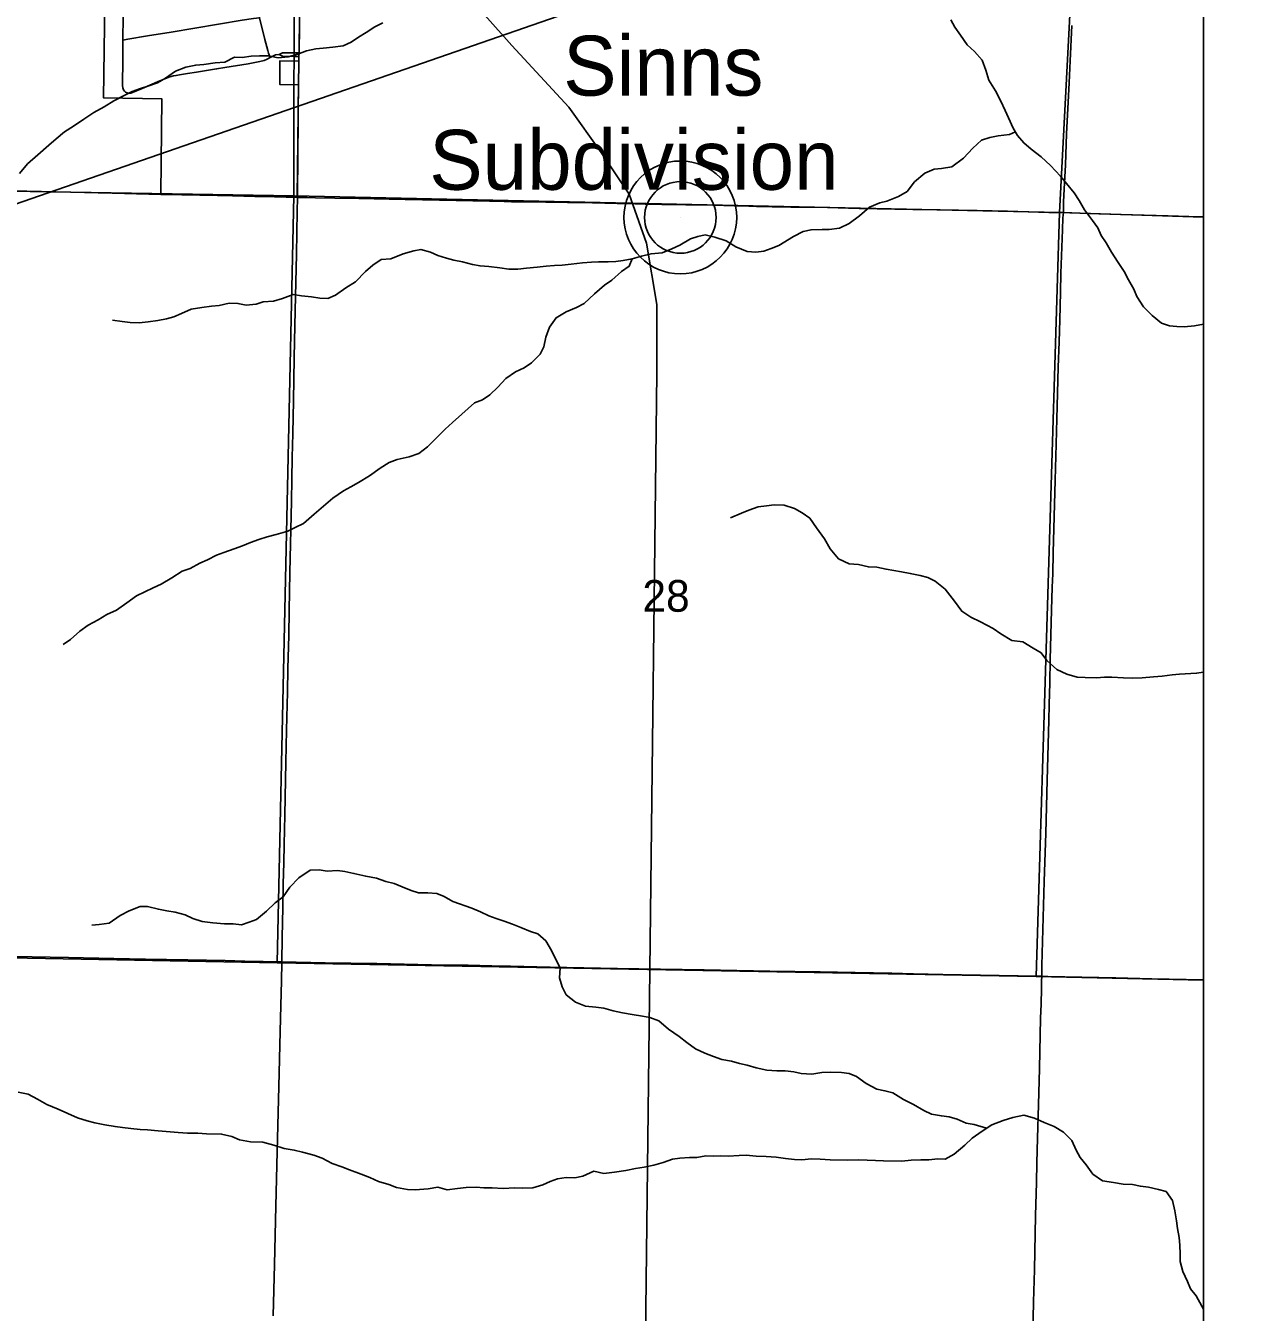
# Model space of a CAD drawing. Extents: x 0 to 34, y 0 to 22.
# Drawn here: x 7.346 to 8.95, y 15.064 to 16.761 of the extents above; entities that cross this region are included whole.
import ezdxf

# ---------------------------------------------------------------- set-up
doc = ezdxf.new("R2010")
doc.units = 0
for name, color, linetype in [('GM_X_City_Street', 7, 'Continuous'), ('GM_X_Corporation', 7, 'Continuous'), ('GM_X_County_Road', 7, 'Continuous'), ('GM_X_Minor_River', 7, 'Continuous'), ('GM_X_Rail_Line', 7, 'Continuous'), ('GM_X_Section_Text', 7, 'Continuous'), ('GM_X_Township_Road', 7, 'Continuous'), ('GM_X_Unincorporated', 7, 'Continuous'), ('GM_X_Unincorporated_Location', 7, 'Continuous'), ('GM_X_Unincorporated_Text', 7, 'Continuous'), ('GM_X_US_Route', 7, 'Continuous'), ('SH_Data', 7, 'Continuous')]:
    doc.layers.add(name, color=color, linetype=linetype)

msp = doc.modelspace()

# ---------------------------------------------------------------- linework, layer by layer
at = {"layer": 'GM_X_City_Street'}
for points in [[(7.6688, 16.7193), (7.6668, 16.7249), (7.6656, 16.7284), (7.6617, 16.743), (7.6546, 16.7718), (7.6511, 16.786), (7.6432, 16.8155), (7.6415, 16.8215), (7.6403, 16.8234), (7.639, 16.8245)], [(7.48, 16.6728), (7.4781, 16.6737), (7.4765, 16.6751), (7.4753, 16.6768), (7.4743, 16.6793), (7.4741, 16.6823), (7.4742, 16.6892), (7.4743, 16.7105), (7.4746, 16.7424), (7.4748, 16.774), (7.475, 16.7901), (7.4749, 16.7932)], [(7.4746, 16.7424), (7.4812, 16.7435), (7.507, 16.7478), (7.5383, 16.7529), (7.632, 16.7685), (7.6468, 16.7706), (7.6546, 16.7718)], [(7.48, 16.6728), (7.4822, 16.6723), (7.4849, 16.6722), (7.4874, 16.673), (7.4999, 16.6784), (7.5233, 16.6884), (7.5364, 16.6938), (7.5412, 16.695), (7.5447, 16.6957), (7.5493, 16.6965), (7.5596, 16.6981), (7.5717, 16.7002), (7.5981, 16.7043), (7.6091, 16.7063), (7.6397, 16.7112), (7.655, 16.714), (7.6611, 16.7156), (7.6647, 16.7171), (7.6681, 16.7189), (7.6688, 16.7193), (7.6724, 16.7212), (7.6758, 16.7227), (7.6806, 16.7234)], [(7.6806, 16.7234), (7.6849, 16.7257), (7.6861, 16.7257), (7.6996, 16.7255), (7.7069, 16.7253)], [(7.6806, 16.7234), (7.685, 16.7211), (7.6995, 16.7208), (7.7068, 16.7206)]]:
    msp.add_lwpolyline(points, dxfattribs=at)
at = {"layer": 'GM_X_Corporation'}
for points in [[(8.9, 14.4942), (8.9, 20.9), (2.1, 20.9)], [(8.9, 14.4942), (8.9, 20.5041)], [(7.4506, 16.7923), (7.4491, 16.6661), (7.5261, 16.6648), (7.5247, 16.5394), (7.7046, 16.5356), (7.7064, 16.6834), (7.6814, 16.6839), (7.6817, 16.7151), (7.7067, 16.7147), (7.7074, 16.7628)]]:
    msp.add_lwpolyline(points, dxfattribs=at)
for points in [[(6.7004, 17.5689), (7.7016, 17.5373), (7.6999, 16.5369), (6.6829, 16.5538)], [(7.7016, 17.5373), (8.7625, 17.5156), (8.7104, 16.5149), (7.6999, 16.5369)], [(8.9, 16.5086), (8.9, 17.5119), (8.7625, 17.5156), (8.7104, 16.5149)], [(6.6829, 16.5538), (7.6999, 16.5369), (7.6779, 15.5253), (6.6666, 15.5439)], [(7.6999, 16.5369), (8.7104, 16.5149), (8.6793, 15.5073), (7.6779, 15.5253)], [(8.9, 15.5025), (8.9, 16.5086), (8.7104, 16.5149), (8.6793, 15.5073)]]:
    msp.add_lwpolyline(points, close=True, dxfattribs=at)
at = {"layer": 'GM_X_County_Road'}
msp.add_line((7.7061, 16.6825), (7.7066, 16.7137), dxfattribs=at)
for points in [[(7.7075, 16.7611), (7.7075, 16.7621), (7.7078, 16.7914), (7.708, 16.8091), (7.7082, 16.8225), (7.7087, 16.8696), (7.7089, 16.8954), (7.7089, 16.9013)], [(7.7068, 16.7206), (7.7069, 16.7253), (7.7075, 16.7611)], [(8.7263, 16.7614), (8.7242, 16.715), (8.7229, 16.6858), (8.7217, 16.6604), (8.7194, 16.6188), (8.7179, 16.5779), (8.7162, 16.5456), (8.7156, 16.5289), (8.7153, 16.5148)], [(7.7066, 16.7137), (7.7067, 16.7162), (7.7068, 16.7206)], [(7.7047, 16.5348), (7.705, 16.5549), (7.7052, 16.5736), (7.7052, 16.5854), (7.7058, 16.6401), (7.7059, 16.6532), (7.7061, 16.6825)], [(7.6843, 15.5265), (7.6848, 15.5585), (7.6856, 15.5983), (7.6861, 15.6294), (7.6868, 15.6573), (7.6874, 15.6811), (7.6881, 15.7201), (7.6897, 15.7897), (7.6905, 15.832), (7.6917, 15.8823), (7.6923, 15.9134), (7.6933, 15.9569), (7.694, 15.9899), (7.695, 16.0402), (7.6969, 16.1341), (7.6975, 16.1633), (7.698, 16.1919), (7.6987, 16.2236), (7.6996, 16.2665), (7.7007, 16.3231), (7.7015, 16.366), (7.7024, 16.4039), (7.7035, 16.4598), (7.7046, 16.5164), (7.7047, 16.5348)], [(8.7153, 16.5148), (8.7479, 16.5138), (8.7907, 16.5124), (8.8535, 16.5106), (8.8945, 16.5092), (8.9, 16.509)], [(7.673, 15.0594), (7.6744, 15.1272), (7.6764, 15.2042), (7.6781, 15.2763), (7.6803, 15.3621), (7.682, 15.4348), (7.6828, 15.469), (7.6838, 15.5013), (7.6843, 15.5255), (7.6843, 15.5265)]]:
    msp.add_lwpolyline(points, dxfattribs=at)
at = {"layer": 'GM_X_Minor_River'}
for points in [[(8.6082, 16.7158), (8.5982, 16.7274), (8.5885, 16.7359), (8.5797, 16.749), (8.5723, 16.7594), (8.5668, 16.7689)], [(7.8174, 16.7653), (7.8071, 16.7598), (7.7955, 16.7524), (7.7856, 16.7462), (7.7756, 16.7395), (7.7652, 16.7348), (7.7515, 16.7328), (7.7386, 16.7315), (7.7291, 16.7306), (7.7169, 16.7281), (7.7055, 16.7238), (7.6925, 16.7203), (7.6792, 16.719), (7.6668, 16.7215), (7.6546, 16.7214), (7.6436, 16.7209), (7.6318, 16.7192), (7.622, 16.7198), (7.609, 16.7132), (7.5961, 16.7123), (7.5812, 16.7103), (7.5706, 16.7094), (7.5576, 16.7066), (7.5439, 16.7012), (7.5308, 16.6919), (7.5201, 16.6861), (7.5075, 16.6814), (7.4976, 16.6785), (7.4869, 16.6746), (7.4773, 16.6695), (7.4627, 16.6621), (7.4497, 16.6544), (7.4363, 16.6467), (7.4232, 16.6379), (7.4094, 16.6287), (7.3975, 16.6213), (7.3867, 16.612), (7.377, 16.6039), (7.3624, 16.5909), (7.3489, 16.579), (7.338, 16.5663)], [(8.9, 16.3676), (8.8881, 16.3654), (8.8745, 16.3642), (8.865, 16.3644), (8.8552, 16.3653), (8.8446, 16.3689), (8.8323, 16.3791), (8.8208, 16.3907), (8.8123, 16.4041), (8.8083, 16.4137), (8.8013, 16.4263), (8.7955, 16.4371), (8.7874, 16.449), (8.7789, 16.4628), (8.7716, 16.4751), (8.7653, 16.4847), (8.7606, 16.4946), (8.7536, 16.5043), (8.7432, 16.5185), (8.7362, 16.5308), (8.7296, 16.5408), (8.7196, 16.5531), (8.7115, 16.5628), (8.6985, 16.5767), (8.6862, 16.5883), (8.6727, 16.5984), (8.663, 16.6066), (8.6549, 16.6166), (8.649, 16.6262), (8.6428, 16.6396), (8.6384, 16.6495), (8.6326, 16.6618), (8.6257, 16.6756), (8.6168, 16.6894), (8.6129, 16.7028), (8.6082, 16.7158)], [(8.652, 16.6212), (8.6443, 16.6179), (8.6294, 16.616), (8.6184, 16.6139), (8.6073, 16.6103), (8.5958, 16.5999), (8.5834, 16.5865), (8.568, 16.575), (8.5547, 16.573), (8.5448, 16.5721), (8.5325, 16.5666), (8.5191, 16.5555), (8.5093, 16.5428), (8.4978, 16.5358), (8.4825, 16.53), (8.473, 16.5275), (8.4596, 16.5221), (8.4465, 16.5106), (8.4327, 16.5002), (8.42, 16.4944), (8.4063, 16.4924), (8.3969, 16.4926), (8.3825, 16.4921), (8.3718, 16.4897), (8.3591, 16.4831), (8.34, 16.4713), (8.3296, 16.4673), (8.3201, 16.4641), (8.3095, 16.4628), (8.2981, 16.4634), (8.2834, 16.4698), (8.2703, 16.4776), (8.2556, 16.4824), (8.2428, 16.4853), (8.2329, 16.4833), (8.2233, 16.48), (8.2091, 16.472), (8.1988, 16.4672), (8.1858, 16.4618), (8.1714, 16.4605), (8.1588, 16.4574), (8.1466, 16.4538), (8.1344, 16.4518), (8.1249, 16.4504), (8.1147, 16.4499), (8.1022, 16.4498), (8.0927, 16.4496), (8.0809, 16.4486), (8.0661, 16.4467), (8.0539, 16.4454), (8.044, 16.4452), (8.033, 16.4443), (8.0212, 16.4426), (8.0072, 16.4414), (7.9954, 16.4401), (7.9837, 16.4403), (7.9719, 16.442), (7.9572, 16.4435), (7.9458, 16.4444), (7.936, 16.4465), (7.9224, 16.4498), (7.9111, 16.4519), (7.9013, 16.4548), (7.89, 16.4584), (7.8802, 16.4624), (7.8677, 16.4661), (7.8582, 16.4644), (7.8441, 16.4605), (7.8281, 16.4539), (7.8151, 16.4527), (7.8044, 16.4453), (7.7948, 16.4371), (7.7816, 16.4234), (7.7685, 16.4156), (7.7551, 16.406), (7.7448, 16.4013), (7.7345, 16.4019), (7.7232, 16.4036), (7.7103, 16.405), (7.699, 16.4068), (7.6852, 16.4013), (7.6734, 16.3978), (7.6597, 16.3969), (7.6502, 16.394), (7.6373, 16.3928), (7.6263, 16.3949), (7.6146, 16.3951), (7.6016, 16.3923), (7.5914, 16.3914), (7.5788, 16.3894), (7.5647, 16.3874), (7.5517, 16.3819), (7.5418, 16.3772), (7.5323, 16.3747), (7.5205, 16.3723), (7.5079, 16.3706), (7.4961, 16.3694), (7.484, 16.37), (7.4738, 16.3713), (7.4609, 16.3731)], [(8.1465, 16.4538), (8.1426, 16.444), (8.1322, 16.437), (8.1195, 16.4255), (8.1099, 16.4192), (8.0968, 16.4077), (8.0833, 16.3947), (8.0729, 16.3896), (8.0595, 16.3838), (8.0461, 16.3761), (8.0375, 16.3637), (8.0327, 16.3506), (8.0298, 16.3377), (8.0251, 16.3279), (8.0135, 16.3164), (8.0039, 16.3098), (7.9924, 16.3047), (7.9797, 16.2958), (7.9693, 16.2846), (7.9585, 16.2746), (7.9488, 16.2676), (7.9385, 16.264), (7.9219, 16.2491), (7.9096, 16.238), (7.8999, 16.2291), (7.8868, 16.2164), (7.8764, 16.206), (7.8648, 16.1971), (7.8522, 16.1928), (7.8362, 16.189), (7.8259, 16.185), (7.814, 16.1777), (7.7998, 16.1677), (7.7852, 16.1589), (7.7752, 16.153), (7.7656, 16.1479), (7.7514, 16.1379), (7.7267, 16.1171), (7.7129, 16.1049), (7.7018, 16.0994), (7.6922, 16.0947), (7.6769, 16.09), (7.6651, 16.0869), (7.6541, 16.0837), (7.643, 16.0797), (7.6323, 16.0754), (7.6212, 16.0714), (7.6078, 16.0664), (7.5979, 16.0627), (7.586, 16.0569), (7.5761, 16.0522), (7.5631, 16.0452), (7.5527, 16.0416), (7.5393, 16.0332), (7.5251, 16.0247), (7.5144, 16.02), (7.5033, 16.0145), (7.4926, 16.0094), (7.4799, 16.0002), (7.466, 15.9902), (7.4534, 15.9848), (7.4419, 15.9778), (7.4289, 15.9708), (7.4177, 15.9627), (7.4054, 15.9516), (7.3958, 15.9453)], [(8.5019, 16.041), (8.4815, 16.0444), (8.4694, 16.0469), (8.458, 16.0475), (8.4452, 16.0504), (8.4327, 16.0514), (8.4188, 16.0582), (8.4077, 16.0713), (8.4, 16.0843), (8.3896, 16.0989), (8.3808, 16.1116), (8.3707, 16.1186), (8.3606, 16.1245), (8.347, 16.129), (8.3337, 16.1292), (8.3235, 16.1279), (8.3128, 16.1266), (8.3002, 16.1223), (8.2907, 16.1183), (8.2761, 16.1121)], [(8.9, 15.9087), (8.891, 15.9071), (8.8683, 15.9061), (8.8588, 15.9051), (8.8458, 15.9035), (8.8341, 15.9025), (8.8192, 15.9013), (8.8067, 15.9008), (8.7946, 15.901), (8.7791, 15.9021), (8.7696, 15.9019), (8.7589, 15.901), (8.7442, 15.9016), (8.7336, 15.9022), (8.72, 15.9059), (8.7068, 15.9122), (8.6934, 15.9239), (8.686, 15.9339), (8.6755, 15.9401), (8.662, 15.9484), (8.6473, 15.9505), (8.6327, 15.9592), (8.6226, 15.9662), (8.606, 15.9752), (8.5933, 15.9812), (8.5813, 15.989), (8.5717, 16.0021), (8.5595, 16.0179), (8.546, 16.0288), (8.5363, 16.0335), (8.5264, 16.036), (8.5132, 16.0389), (8.5019, 16.041)], [(8.614, 15.3069), (8.5974, 15.3121), (8.5871, 15.3135), (8.5751, 15.319), (8.5646, 15.3219), (8.5543, 15.3232), (8.5415, 15.3257), (8.5314, 15.3305), (8.5175, 15.3383), (8.5043, 15.345), (8.4905, 15.3536), (8.4799, 15.3565), (8.469, 15.3586), (8.4551, 15.3661), (8.4424, 15.3754), (8.4326, 15.379), (8.4224, 15.3807), (8.4083, 15.381), (8.3966, 15.3805), (8.3833, 15.3785), (8.3696, 15.3791), (8.3598, 15.3812), (8.3481, 15.3826), (8.3371, 15.3828), (8.3242, 15.3838), (8.3099, 15.3867), (8.2982, 15.3904), (8.288, 15.3925), (8.2774, 15.3953), (8.2646, 15.3978), (8.2536, 15.4018), (8.2423, 15.4059), (8.2299, 15.4118), (8.2187, 15.4203), (8.2083, 15.4281), (8.1944, 15.4375), (8.1814, 15.4487), (8.1697, 15.4531), (8.1599, 15.4549), (8.1466, 15.457), (8.1338, 15.4592), (8.1213, 15.462), (8.1089, 15.4653), (8.0983, 15.4667), (8.085, 15.4681), (8.0715, 15.4733), (8.0595, 15.483), (8.0541, 15.4937), (8.0505, 15.5055), (8.0515, 15.5184), (8.0453, 15.5306), (8.0398, 15.5414), (8.0325, 15.554), (8.022, 15.5633), (8.0122, 15.5666), (7.9995, 15.5717), (7.9885, 15.5761), (7.9776, 15.5801), (7.9671, 15.5837), (7.9573, 15.5873), (7.9464, 15.5925), (7.9347, 15.5973), (7.9099, 15.6061), (7.8986, 15.6128), (7.8888, 15.6167), (7.8767, 15.6174), (7.8646, 15.6176), (7.8548, 15.6204), (7.8431, 15.6256), (7.8326, 15.63), (7.8216, 15.6325), (7.8092, 15.6369), (7.7949, 15.6394), (7.7794, 15.6431), (7.7673, 15.6456), (7.7575, 15.647), (7.7442, 15.6461), (7.7336, 15.6478), (7.7214, 15.6473), (7.7065, 15.6374), (7.6948, 15.6251), (7.6859, 15.6123), (7.6755, 15.6042), (7.6639, 15.5934), (7.6508, 15.5823), (7.6412, 15.5787), (7.6309, 15.5755), (7.62, 15.5768), (7.6086, 15.5767), (7.5931, 15.5781), (7.5791, 15.5795), (7.567, 15.5836), (7.5565, 15.5883), (7.5433, 15.592), (7.5327, 15.5937), (7.5214, 15.5958), (7.507, 15.5995), (7.4972, 15.5993), (7.483, 15.5939), (7.4708, 15.5877), (7.4565, 15.5777)], [(7.4565, 15.5777), (7.4432, 15.5757), (7.4337, 15.5748)], [(8.4781, 15.264), (8.4675, 15.2646), (8.4565, 15.2648), (8.4451, 15.2654), (8.4304, 15.2649), (8.4076, 15.2654), (8.3944, 15.2664), (8.383, 15.2666), (8.3704, 15.2653), (8.3606, 15.2659), (8.3489, 15.2673), (8.3364, 15.2687), (8.3231, 15.2697), (8.3102, 15.2703), (8.297, 15.2713), (8.2875, 15.2711), (8.2731, 15.2703), (8.2632, 15.2705), (8.2537, 15.2703), (8.2435, 15.2705), (8.2317, 15.2684), (8.2219, 15.2682), (8.2093, 15.2677), (8.1998, 15.2664), (8.1872, 15.2617), (8.175, 15.2585), (8.1621, 15.2557), (8.151, 15.254), (8.1381, 15.2513), (8.1229, 15.2489), (8.1092, 15.2473), (8.096, 15.2502), (8.0815, 15.2436), (8.0708, 15.2416), (8.0594, 15.2422), (8.048, 15.2401), (8.0381, 15.2369), (8.0285, 15.2325), (8.0152, 15.2286), (8.0019, 15.2281), (7.9917, 15.2283), (7.9761, 15.2275), (7.9617, 15.2285), (7.9507, 15.2284), (7.9405, 15.2293), (7.9276, 15.2288), (7.9162, 15.2275), (7.9025, 15.2259), (7.8901, 15.2292), (7.8771, 15.2271), (7.86, 15.2259), (7.8502, 15.2261), (7.8354, 15.2287), (7.8253, 15.2327), (7.8117, 15.2367), (7.8004, 15.2419), (7.7891, 15.2463), (7.7737, 15.2523), (7.7632, 15.2559), (7.7507, 15.2607), (7.7376, 15.2674), (7.7263, 15.2714), (7.7116, 15.2755), (7.7006, 15.2783), (7.6874, 15.2805), (7.6735, 15.2849), (7.6591, 15.2886), (7.6428, 15.2893), (7.6285, 15.2919), (7.6183, 15.2962), (7.6047, 15.2992), (7.585, 15.2995), (7.5733, 15.3005), (7.56, 15.3004), (7.5475, 15.3014), (7.5316, 15.3029), (7.521, 15.3034), (7.507, 15.3048), (7.4972, 15.3054), (7.4851, 15.3068), (7.4741, 15.3078), (7.4642, 15.3091), (7.4506, 15.3116), (7.4374, 15.3142), (7.4276, 15.3166), (7.4148, 15.3207), (7.402, 15.3266), (7.3892, 15.3322), (7.3742, 15.3385), (7.3618, 15.3452), (7.3494, 15.3519), (7.3366, 15.3544)], [(8.9, 15.0678), (8.898, 15.0724), (8.8903, 15.0858), (8.8829, 15.0954), (8.8789, 15.105), (8.8727, 15.118), (8.8692, 15.1313), (8.8693, 15.1408), (8.8688, 15.1529), (8.8679, 15.1628), (8.8658, 15.1746), (8.8645, 15.1849), (8.8625, 15.1982), (8.8593, 15.2115), (8.8508, 15.2234), (8.8407, 15.2263), (8.8278, 15.2292), (8.8169, 15.2305), (8.8067, 15.2326), (8.7942, 15.2332), (8.7813, 15.2354), (8.7669, 15.2376), (8.7542, 15.2465), (8.7454, 15.2588), (8.7376, 15.2685), (8.7321, 15.2781), (8.7266, 15.2907), (8.7155, 15.3019), (8.7031, 15.3093), (8.6899, 15.3145), (8.6771, 15.3201), (8.6632, 15.3241), (8.6487, 15.321), (8.6358, 15.3171), (8.6209, 15.3113), (8.6082, 15.3032), (8.5951, 15.294), (8.5855, 15.2847), (8.5712, 15.2728), (8.5593, 15.2662), (8.5495, 15.2668), (8.5377, 15.2655), (8.5271, 15.2653), (8.5145, 15.2648), (8.502, 15.2636), (8.4781, 15.264)]]:
    msp.add_lwpolyline(points, dxfattribs=at)
at = {"layer": 'GM_X_Rail_Line'}
msp.add_lwpolyline([(8.1578, 14.5086), (8.1698, 15.5158), (8.179, 16.303), (8.179, 16.3934), (8.1652, 16.4746), (8.1423, 16.5389), (8.1055, 16.594), (8.0627, 16.6538), (7.9876, 16.735), (7.8453, 16.8958), (7.7917, 16.9478), (7.7304, 16.9923), (7.6677, 17.0229), (7.5972, 17.0673), (7.5441, 17.1046)], dxfattribs=at)
at = {"layer": 'GM_X_Township_Road'}
for points in [[(7.2752, 16.5446), (7.3029, 16.5439), (7.3259, 16.5435), (7.3477, 16.5429), (7.4055, 16.5418), (7.4602, 16.5405), (7.5248, 16.5387)], [(7.5248, 16.5387), (7.5522, 16.5384), (7.5994, 16.5373), (7.6193, 16.5368), (7.6485, 16.536), (7.6745, 16.5357), (7.7047, 16.5348)], [(7.7047, 16.5348), (7.7145, 16.5347), (7.7176, 16.5347), (7.7288, 16.5344), (7.7542, 16.5337), (7.7859, 16.5332), (7.8257, 16.5325), (7.8469, 16.5321), (7.8922, 16.5311), (7.9581, 16.5297), (7.9775, 16.5293), (7.9873, 16.5291), (8.0041, 16.529), (8.0613, 16.5281), (8.0943, 16.5275), (8.1266, 16.5269), (8.1346, 16.5269), (8.1365, 16.5269), (8.1636, 16.5261), (8.1855, 16.5256), (8.2172, 16.5251), (8.2527, 16.5245), (8.2813, 16.5237), (8.2903, 16.5235)], [(8.2903, 16.5235), (8.3105, 16.5229), (8.331, 16.5225), (8.3558, 16.522), (8.4043, 16.5213), (8.446, 16.5204), (8.5169, 16.519), (8.5529, 16.5183), (8.6014, 16.5175), (8.6418, 16.5166), (8.6959, 16.5151), (8.7153, 16.5148)], [(8.6867, 15.5074), (8.687, 15.5218), (8.6901, 15.6324), (8.6921, 15.6964), (8.6938, 15.7661), (8.696, 15.845), (8.6966, 15.8661), (8.6973, 15.8947), (8.698, 15.9252), (8.6997, 15.9904), (8.7006, 16.0209), (8.7012, 16.0383), (8.702, 16.0662), (8.7045, 16.162), (8.7058, 16.2092), (8.7072, 16.2595), (8.7085, 16.3111), (8.7096, 16.3441), (8.7105, 16.3733), (8.7114, 16.4099), (8.7121, 16.4348), (8.714, 16.492), (8.7148, 16.508), (8.7153, 16.5148)], [(8.6616, 14.4986), (8.6623, 14.5194), (8.6639, 14.5783), (8.6649, 14.6206), (8.6669, 14.7138), (8.6691, 14.7965), (8.6705, 14.8667), (8.6728, 14.9568), (8.6745, 15.0128), (8.6759, 15.078), (8.677, 15.1203), (8.6787, 15.1918), (8.6798, 15.2353), (8.6804, 15.2614), (8.6811, 15.2937), (8.6825, 15.3378), (8.684, 15.3857), (8.6853, 15.4522), (8.6859, 15.4708), (8.6864, 15.4914), (8.6865, 15.5008), (8.6867, 15.5074)]]:
    msp.add_lwpolyline(points, dxfattribs=at)
at = {"layer": 'GM_X_Unincorporated'}
for radius in [0.0744, 0.0472]:
    msp.add_circle((8.21, 16.5084), radius, dxfattribs=at)
at = {"layer": 'GM_X_Unincorporated_Location'}
msp.add_line((8.21, 16.5084), (8.21, 16.5084), dxfattribs=at)
at = {"layer": 'GM_X_US_Route'}
msp.add_lwpolyline([(7.2582, 15.535), (7.403, 15.5321), (7.4627, 15.531), (7.5043, 15.5302), (7.5603, 15.529), (7.6094, 15.5282), (7.6355, 15.5273), (7.6843, 15.5265), (7.7412, 15.5254), (7.8096, 15.5242), (7.8817, 15.5227), (7.9302, 15.5219), (7.9612, 15.5212), (7.9861, 15.5207), (8.0383, 15.5194), (8.1272, 15.5178), (8.1838, 15.5167), (8.2416, 15.5158), (8.328, 15.5143), (8.3945, 15.5134), (8.4405, 15.5123), (8.489, 15.5115), (8.5176, 15.5108), (8.5562, 15.51), (8.6556, 15.5082), (8.6867, 15.5074), (8.6948, 15.5072), (8.7843, 15.5052), (8.8322, 15.5042), (8.9, 15.5027)], dxfattribs=at)
at = {"layer": 'SH_Data'}
msp.add_line((8.9, 20.9), (8.9, 14.1), dxfattribs=at)
msp.add_lwpolyline([(4.574, 15.5703), (9.2813, 17.2011), (9.2813, 17.6911)], close=True, dxfattribs=at)

# ---------------------------------------------------------------- texts
at = {"layer": 'GM_X_Section_Text'}
msp.add_text('28', height=0.04186, rotation=0, dxfattribs=at).set_placement((8.16, 15.9883))
at = {"layer": 'GM_X_Unincorporated_Text'}
for s, height, p in [('Sinns', 0.07898, (8.0554, 16.6691)), ('Subdivision', 0.078977, (7.8787, 16.5449))]:
    msp.add_text(s, height=height, rotation=0, dxfattribs=at).set_placement(p)

doc.saveas('drawing.dxf')
